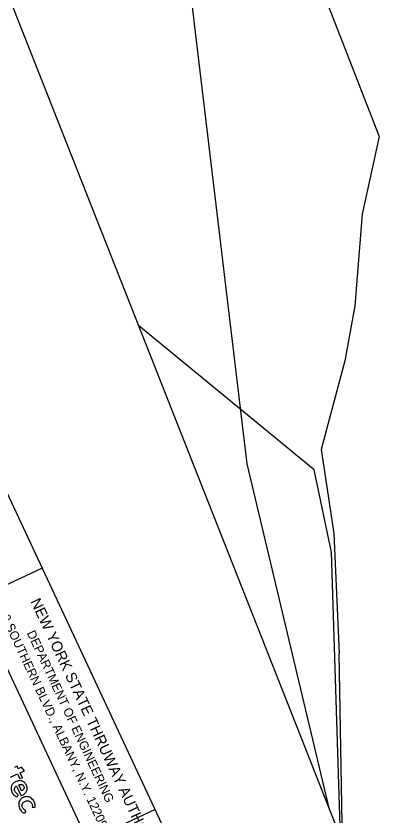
# Model space of a CAD drawing. Extents: x 1040364 to 1041050, y 1127298 to 1128100.
# Drawn here: x 1040605.1 to 1040706.7, y 1127434.3 to 1127649.8 of the extents above; entities that cross this region are included whole.
import ezdxf

# ---------------------------------------------------------------- set-up
doc = ezdxf.new("R2010")
doc.units = 0
for name, color, linetype in [('AC_P', 7, 'Continuous'), ('clip boundary', 7, 'Continuous'), ('G-ANNO-LOGO', 7, 'Continuous'), ('LAWA', 7, 'Continuous'), ('LELB', 7, 'Continuous'), ('MHB', 7, 'Continuous'), ('SHEET_BORDER', 7, 'Continuous')]:
    doc.layers.add(name, color=color, linetype=linetype)

msp = doc.modelspace()

# ---------------------------------------------------------------- linework, layer by layer
at = {"layer": 'AC_P'}
msp.add_arc((1045321.32, 1129655.39), 5000, 200.40109, 205.67201, dxfattribs=at)
at = {"layer": 'clip boundary'}
msp.add_lwpolyline([(1040504.79, 1127904.67), (1040760.34, 1127999.71), (1040984.84, 1127512.73), (1040710.81, 1127382.18)], close=True, dxfattribs=at)
at = {"layer": 'G-ANNO-LOGO'}
for p, q in [((1040605.46, 1127447.47), (1040604.73, 1127447.13)), ((1040605.77, 1127446.81), (1040605.46, 1127447.47)), ((1040606.65, 1127447.21), (1040605.77, 1127446.81)), ((1040607.43, 1127446.3), (1040606.65, 1127447.21)), ((1040603.67, 1127444.57), (1040605.53, 1127445.42)), ((1040605.53, 1127445.42), (1040606.05, 1127444.3)), ((1040606.26, 1127445.75), (1040607.43, 1127446.3)), ((1040606.9, 1127444.39), (1040606.26, 1127445.75)), ((1040606.05, 1127444.3), (1040606.9, 1127444.39)), ((1040605.25, 1127442.16), (1040606.5, 1127439.49)), ((1040606.64, 1127440.85), (1040605.89, 1127442.46)), ((1040609.54, 1127436.37), (1040610.33, 1127436.45))]:
    msp.add_line(p, q, dxfattribs=at)
for points in [[(1040606.5, 1127439.49), (1040606.6, 1127439.53), (1040606.86, 1127439.64), (1040607.25, 1127439.88), (1040607.66, 1127440.2), (1040607.92, 1127440.59), (1040608.11, 1127440.98), (1040608.18, 1127441.4), (1040608.15, 1127441.88), (1040607.97, 1127442.35), (1040607.75, 1127442.79), (1040607.42, 1127443.15), (1040607.04, 1127443.41), (1040606.6, 1127443.59), (1040606.14, 1127443.63), (1040605.68, 1127443.57), (1040605.25, 1127443.42), (1040604.81, 1127443.22), (1040604.45, 1127442.94), (1040604.13, 1127442.59), (1040603.91, 1127442.19), (1040603.82, 1127441.69), (1040603.8, 1127441.12), (1040604.03, 1127440.57), (1040604.26, 1127440.09), (1040604.54, 1127439.71), (1040604.86, 1127439.46), (1040605.18, 1127439.31), (1040605.44, 1127439.33), (1040605.6, 1127439.46), (1040605.71, 1127439.62), (1040605.68, 1127439.78), (1040605.63, 1127439.93), (1040605.51, 1127440.07), (1040605.29, 1127440.21), (1040605.06, 1127440.37), (1040604.87, 1127440.61), (1040604.74, 1127440.86), (1040604.69, 1127441.14), (1040604.74, 1127441.41), (1040604.81, 1127441.69), (1040604.97, 1127441.92), (1040605.12, 1127442.07), (1040605.22, 1127442.14), (1040605.25, 1127442.16)], [(1040605.89, 1127442.46), (1040605.92, 1127442.48), (1040606.01, 1127442.52), (1040606.17, 1127442.58), (1040606.39, 1127442.62), (1040606.66, 1127442.59), (1040606.93, 1127442.48), (1040607.15, 1127442.26), (1040607.29, 1127441.97), (1040607.33, 1127441.67), (1040607.29, 1127441.38), (1040607.09, 1127441.15), (1040606.87, 1127440.98), (1040606.71, 1127440.89), (1040606.64, 1127440.85)], [(1040610.33, 1127436.45), (1040610.34, 1127436.57), (1040610.36, 1127436.84), (1040610.28, 1127437.32), (1040610.08, 1127437.88), (1040609.75, 1127438.42), (1040609.32, 1127438.87), (1040608.82, 1127439.18), (1040608.26, 1127439.31), (1040607.7, 1127439.3), (1040607.14, 1127439.12), (1040606.63, 1127438.83), (1040606.24, 1127438.43), (1040606, 1127437.99), (1040605.86, 1127437.47), (1040605.86, 1127436.85), (1040606.04, 1127436.21), (1040606.33, 1127435.68), (1040606.67, 1127435.28), (1040607, 1127435), (1040607.33, 1127434.87), (1040607.55, 1127434.95), (1040607.7, 1127435.05), (1040607.75, 1127435.2), (1040607.77, 1127435.34), (1040607.72, 1127435.47), (1040607.61, 1127435.62), (1040607.42, 1127435.71), (1040607.23, 1127435.88), (1040607.03, 1127436.05), (1040606.86, 1127436.34), (1040606.74, 1127436.67), (1040606.77, 1127437.06), (1040606.89, 1127437.39), (1040607.08, 1127437.71), (1040607.38, 1127437.92), (1040607.68, 1127438.12), (1040608.05, 1127438.17), (1040608.4, 1127438.19), (1040608.72, 1127438.11), (1040609.01, 1127437.95), (1040609.25, 1127437.72), (1040609.43, 1127437.41), (1040609.55, 1127437.06), (1040609.6, 1127436.7), (1040609.56, 1127436.47), (1040609.54, 1127436.37)]]:
    msp.add_open_spline(points, degree=3, dxfattribs=at)
at = {"layer": 'LAWA'}
msp.add_lwpolyline([(1040692.56, 1127428.47), (1040690.16, 1127505.27), (1040685.49, 1127527.45), (1040638.23, 1127566.26)], dxfattribs=at)
at = {"layer": 'LELB'}
for points in [[(1040614.83, 1127854.62), (1040621.41, 1127837.65), (1040627.08, 1127815.86), (1040634.65, 1127795.46), (1040645.6, 1127772.71), (1040652.36, 1127757.32), (1040657.51, 1127737.76), (1040666.51, 1127712.78), (1040677.3, 1127685.09), (1040689.11, 1127653.1), (1040703.01, 1127617.33), (1040698.4, 1127596.43), (1040696.45, 1127571.66), (1040693.76, 1127556.81), (1040687.36, 1127532.93), (1040690.81, 1127510.27), (1040692.18, 1127477.93)], [(1040693.16, 1127426.93), (1040692.18, 1127477.93)]]:
    msp.add_lwpolyline(points, dxfattribs=at)
at = {"layer": 'MHB'}
msp.add_lwpolyline([(1040689.65, 1127435.84), (1040667.39, 1127529.05), (1040645.74, 1127710.89), (1040582.66, 1127929.61), (1040581.63, 1127933.24)], dxfattribs=at)
at = {"layer": 'SHEET_BORDER'}
for p, q in [((1040686.67, 1127341.52), (1040544.54, 1127645.78)), ((1040612.2, 1127500.93), (1040575.96, 1127484)), ((1040654.92, 1127362.22), (1040594.08, 1127492.46)), ((1040642.62, 1127435.81), (1040606.38, 1127418.88))]:
    msp.add_line(p, q, dxfattribs=at)

# ---------------------------------------------------------------- texts
for s, height, p in [('NEW YORK STATE THRUWAY AUTHORITY', 2.88, (1040608.96, 1127491.97)), ('200 SOUTHERN BLVD., ALBANY, N.Y. 12209', 2.4, (1040599.61, 1127490.98)), ('DEPARTMENT OF ENGINEERING', 2.4, (1040608, 1127483.45))]:
    msp.add_text(s, height=height, rotation=295.0387, dxfattribs=at).set_placement(p)

doc.saveas('drawing.dxf')
